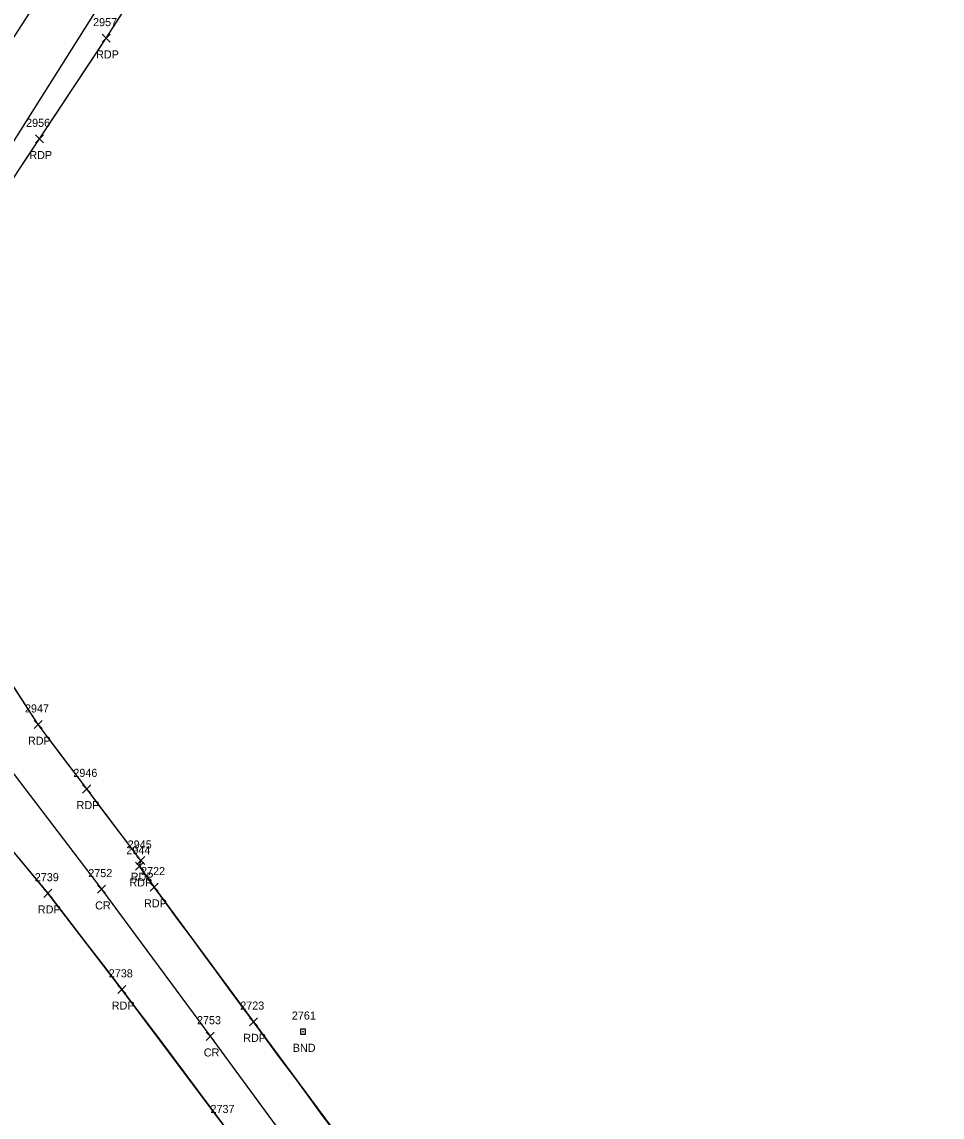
# Model space of a CAD drawing. Extents: x 1638344 to 1639591, y 610835 to 612202.
# Drawn here: x 1639198.8 to 1639426.9, y 611110.8 to 611382.3 of the extents above; entities that cross this region are included whole.
import ezdxf

# ---------------------------------------------------------------- set-up
doc = ezdxf.new("R2010")
doc.units = 0
for name, color, linetype in [('Level 18', 7, 'Continuous'), ('LSOGP', 7, 'Continuous'), ('M_A', 7, 'Continuous'), ('M_I', 7, 'Continuous'), ('P_A', 7, 'Continuous'), ('P_I', 7, 'Continuous'), ('P_TIC', 7, 'Continuous'), ('PET', 7, 'Continuous'), ('PRC', 7, 'Continuous')]:
    doc.layers.add(name, color=color, linetype=linetype)

msp = doc.modelspace()

# ---------------------------------------------------------------- linework, layer by layer
at = {"layer": 'Level 18'}
for p, q in [((1639269.13, 611132.63), (1639267.88, 611132.63)), ((1639267.88, 611132.63), (1639267.88, 611131.38)), ((1639269.13, 611132.63), (1639267.88, 611132.63)), ((1639267.88, 611132.63), (1639267.88, 611131.38)), ((1639269.13, 611131.38), (1639269.13, 611132.63)), ((1639269.13, 611131.38), (1639269.13, 611132.63)), ((1639267.88, 611131.38), (1639269.13, 611131.38)), ((1639267.88, 611131.38), (1639269.13, 611131.38))]:
    msp.add_line(p, q, dxfattribs=at)
msp.add_circle((1639268.48, 611131.97), 0.0833, dxfattribs=at)
at = {"layer": 'LSOGP'}
for points in [[(1639197.65, 611344.93), (1639200.42, 611349.11), (1639203.19, 611353.29), (1639207.33, 611359.53), (1639211.47, 611365.77), (1639215.6, 611372.01), (1639219.74, 611378.25), (1639224.6, 611385.86)], [(1639276.71, 611106.7), (1639273.29, 611111.32), (1639269.88, 611115.95), (1639266.46, 611120.58), (1639263.04, 611125.2), (1639259.62, 611129.83), (1639256.21, 611134.45), (1639253.13, 611138.62), (1639250.06, 611142.79), (1639246.99, 611146.96), (1639243.92, 611151.13), (1639240.84, 611155.29), (1639237.77, 611159.46), (1639234.7, 611163.63), (1639231.63, 611167.8), (1639227.99, 611172.98), (1639228.32, 611174.39), (1639224.97, 611178.83), (1639221.61, 611183.27), (1639218.26, 611187.7), (1639214.9, 611192.14), (1639208.88, 611200.12), (1639202.86, 611208.11), (1639199.81, 611212.83), (1639196.76, 611217.55)], [(1639193.74, 611180.2), (1639199.52, 611173.24), (1639205.3, 611166.28), (1639209.88, 611160.32), (1639214.47, 611154.36), (1639219.05, 611148.4), (1639223.63, 611142.45), (1639226.78, 611138.24), (1639229.93, 611134.04), (1639233.08, 611129.84), (1639236.23, 611125.63), (1639239.39, 611121.43), (1639242.54, 611117.22), (1639245.69, 611113.02), (1639248.84, 611108.82)]]:
    msp.add_lwpolyline(points, dxfattribs=at)
at = {"layer": 'P_TIC'}
for points in [[(1639218.74, 611377.25), (1639220.74, 611379.25)], [(1639220.74, 611377.25), (1639218.74, 611379.25)], [(1639202.19, 611352.29), (1639204.19, 611354.29)], [(1639204.19, 611352.29), (1639202.19, 611354.29)], [(1639201.86, 611207.11), (1639203.86, 611209.11)], [(1639203.86, 611207.11), (1639201.86, 611209.11)], [(1639213.9, 611191.14), (1639215.9, 611193.14)], [(1639215.9, 611191.14), (1639213.9, 611193.14)], [(1639227.32, 611173.39), (1639229.32, 611175.39)], [(1639229.32, 611173.39), (1639227.32, 611175.39)], [(1639226.99, 611171.98), (1639228.99, 611173.98)], [(1639228.99, 611171.98), (1639226.99, 611173.98)], [(1639204.3, 611165.28), (1639206.3, 611167.28)], [(1639206.3, 611165.28), (1639204.3, 611167.28)], [(1639217.55, 611166.29), (1639219.55, 611168.28)], [(1639219.55, 611166.29), (1639217.55, 611168.28)], [(1639230.63, 611166.8), (1639232.63, 611168.8)], [(1639232.63, 611166.8), (1639230.63, 611168.8)], [(1639222.63, 611141.45), (1639224.63, 611143.45)], [(1639224.63, 611141.45), (1639222.63, 611143.45)], [(1639255.21, 611133.45), (1639257.21, 611135.45)], [(1639257.21, 611133.45), (1639255.21, 611135.45)], [(1639244.49, 611129.83), (1639246.49, 611131.83)], [(1639246.49, 611129.83), (1639244.49, 611131.83)]]:
    msp.add_lwpolyline(points, dxfattribs=at)
at = {"layer": 'PET'}
for points in [[(1639227.99, 611172.98), (1639228.32, 611174.39), (1639214.9, 611192.14), (1639202.86, 611208.11), (1639190.66, 611227), (1639183.08, 611239.21), (1639162.79, 611271), (1639160.92, 611274.86), (1639160.06, 611279.39), (1639160.11, 611285.35), (1639161.85, 611291.07), (1639181.02, 611319.86), (1639203.19, 611353.29), (1639219.74, 611378.25), (1639229.46, 611393.47)], [(1638878.4, 610839.82), (1638902.26, 610883.1), (1638925.76, 610925.07), (1638957.26, 610978.12), (1638978.73, 611014.12), (1639004.29, 611055.33), (1639040.97, 611112.29), (1639073.41, 611162.89), (1639102.56, 611207.56), (1639124.27, 611240.99), (1639140.69, 611264.29), (1639156.2, 611287.4), (1639175.63, 611318.1), (1639189.77, 611341.61), (1639219.88, 611389.38)], [(1639410.83, 610892.36), (1639390.46, 610919.54), (1639371.81, 610946.36), (1639349.88, 610975.69), (1639327.19, 611005.39), (1639302.76, 611038.38), (1639275.03, 611075.51), (1639248.84, 611108.82), (1639223.63, 611142.45), (1639205.3, 611166.28), (1639182.19, 611194.12), (1639165.68, 611212.04), (1639150.22, 611225.99), (1639136.41, 611234.04), (1639135.29, 611232.53), (1639130.93, 611235.27), (1639127.56, 611237.67), (1639124.14, 611238.64)], [(1639227.99, 611172.98), (1639231.63, 611167.8)], [(1639231.63, 611167.8), (1639256.21, 611134.45), (1639283.55, 611097.45), (1639314.64, 611056), (1639346.73, 611013.83), (1639378.41, 610971.72), (1639408.01, 610931.01), (1639426.87, 610904.62)]]:
    msp.add_lwpolyline(points, dxfattribs=at)
at = {"layer": 'PRC'}
for points in [[(1639222.36, 611418.19), (1639195.34, 611376.27), (1639169.71, 611336.75), (1639147.17, 611302.78), (1639120.59, 611261.17), (1639092.55, 611217.83), (1639063.71, 611172.41), (1639032.46, 611123.7), (1639004.79, 611080.3), (1638977.88, 611037.27), (1638950.44, 610992.13), (1638925.95, 610950.29), (1638900.28, 610905.37), (1638879.75, 610869.2), (1638867.14, 610846.08)], [(1639145.03, 611260.3), (1639159.75, 611243.63), (1639188.7, 611206.44), (1639218.55, 611167.29), (1639245.48, 611130.83), (1639271.83, 611094.92), (1639293.45, 611066.85), (1639319.08, 611033.06), (1639349.49, 610993.07), (1639374.15, 610959.6), (1639396.77, 610928.59), (1639419.08, 610897.87)]]:
    msp.add_lwpolyline(points, dxfattribs=at)

# ---------------------------------------------------------------- texts
at = {"layer": 'M_A'}
msp.add_text('BND', height=2, dxfattribs=at).set_placement((1639265.97, 611126.98))
at = {"layer": 'M_I'}
msp.add_text('2761', height=2, dxfattribs=at).set_placement((1639265.74, 611134.98))
at = {"layer": 'P_A'}
for s, p in [('RDP', (1639217.23, 611373.25)), ('RDP', (1639200.68, 611348.29)), ('RDP', (1639200.35, 611203.11)), ('RDP', (1639212.39, 611187.14)), ('RDP', (1639225.48, 611167.98)), ('RDP', (1639225.81, 611169.39)), ('CR', (1639216.99, 611162.28)), ('RDP', (1639229.11, 611162.8)), ('RDP', (1639202.79, 611161.28)), ('RDP', (1639221.12, 611137.45)), ('RDP', (1639253.69, 611129.45)), ('CR', (1639243.92, 611125.83))]:
    msp.add_text(s, height=2, dxfattribs=at).set_placement(p)
at = {"layer": 'P_I'}
for s, p in [('2957', (1639216.48, 611381.25)), ('2956', (1639199.88, 611356.29)), ('2947', (1639199.6, 611211.11)), ('2946', (1639211.59, 611195.14)), ('2944', (1639224.73, 611175.98)), ('2945', (1639225.06, 611177.39)), ('2752', (1639215.29, 611170.29)), ('2722', (1639228.37, 611170.8)), ('2739', (1639202.03, 611169.28)), ('2738', (1639220.37, 611145.45)), ('2723', (1639252.95, 611137.45)), ('2753', (1639242.23, 611133.83)), ('2737', (1639245.58, 611111.82))]:
    msp.add_text(s, height=2, dxfattribs=at).set_placement(p)

doc.saveas('drawing.dxf')
